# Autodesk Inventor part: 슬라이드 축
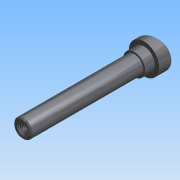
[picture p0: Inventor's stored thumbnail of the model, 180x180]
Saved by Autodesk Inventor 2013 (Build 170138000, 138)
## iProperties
Company: 한국ATC센터
Created: 2014-07
Part Number: 슬라이드 축
Document SubType Name: 모델링
Designer: KYOUNG IL JANG
Mass: 169.556 g
Surface Area: 67.5858 cm^2
Volume: 21.572 cm^3
Density: 7.86 g/cm^3
Material: 강철, 연강
변환 표준: STEP AP214IS
파일 이름: C:\Users\SeoGD\Desktop\?쒗뿕\異?stp
전처리기: Build: 253, Release: 2010 SP1 - Date: Wed 07/29/2009
전송 단위: 밀리미터
불확실성: 0.01
Author: KYOUNG IL JANG
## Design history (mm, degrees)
sketch "스케치1"
  geometry: L1 (0, 100)-(7.5, 100); L2 (7.5, 100)-(7.5, 0); L3 (7.5, 0)-(12.5, 0); L4 (12.5, 0)-(12.5, -17); L5 (12.5, -17)-(0, -17); L6 (0, -17)-(0, 100); 1 further point
  constraints: 12 end point, 2 parallel, 2 point on line, 1 perpendicular, 1 vertical
  dimensions: "d0" = 100 distance from line of L1 point (0, 0); "d1" = 15 diameter of L2 L6; "d2" = 25 diameter of L4 L6; "d3" = 17 distance of L3.end L4.end
revolve "회전1" sketch "스케치1" stored, may be unused: angle "d4" = 90 deg
sketch "스케치2"
  geometry: L1 (12.5, 0)-(12.5, -17) reference; L2 (-12.5, -17)-(12.5, -17) reference; L3 (-12.5, 0)-(-12.5, -17) reference; L4 (12.5, -5)-(-12.5, -11.699); L5 (-12.5, 0)-(12.5, 0) reference; 1 further point
  constraints: 2 end point, 2 point on line
  dimensions: "d5" = 75 deg angle of L1 L4; "d6" = 5 distance from line of L4.start L5
extrude "돌출1" cut sketch "스케치2" stored distance "d7" = 10; taper "d8" = 0 deg
chamfer "모따기1" distance "d9" = 1; stored, may be unused: second distance "d10" = 2, angle "d11" = 45 deg
fillet "모깎기1" dims "d12" = 0.5
hole "구멍1" diameter "d15" = 6.647; stored, may be unused: countersink angle "d19" = 90 deg, drill point angle "d21" = 118 deg; dims "d13" = 10, "d14" = 10, "d16" = 17, "d17" = 4, "d18" = 2, "d20" = 20
chamfer "모따기2" distance "d22" = 1; stored, may be unused: second distance "d23" = 2, angle "d24" = 45 deg
sketch "스케치3"
  geometry: C1 r 9 at (0, 0); 1 further point
  constraints: 1 centre point, 1 coincident
  dimensions: "d25" = 18 diameter of C1
extrude "돌출2" join sketch "스케치3" distance "d26" = 8; taper "d27" = 0 deg
node "솔리드1"
node "솔리드 본체"
node "곡면 본체"
node "솔리드2"
